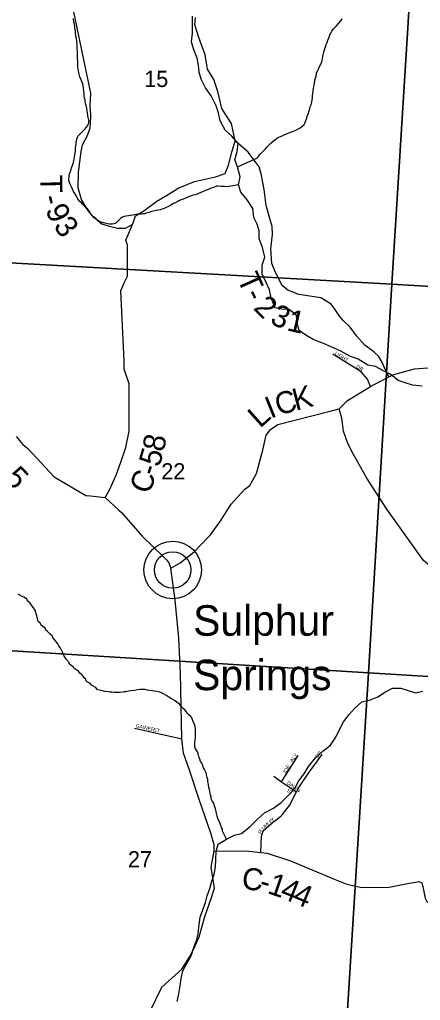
# Model space of a CAD drawing. Extents: x 1949938.81 to 1949945.61, y 152207.65 to 152214.09.
# Drawn here: x 1949942.704 to 1949943.741, y 152210.239 to 152212.776 of the extents above; entities that cross this region are included whole.
import ezdxf

# ---------------------------------------------------------------- set-up
doc = ezdxf.new("R2010")
doc.units = 0
for name, color, linetype in [('GM_X_County_Road', 7, 'Continuous'), ('GM_X_County_Road_Text', 7, 'Continuous'), ('GM_X_Minor_River', 7, 'Continuous'), ('GM_X_Section', 7, 'Continuous'), ('GM_X_Section_Text', 7, 'Continuous'), ('GM_X_Township_Road', 7, 'Continuous'), ('GM_X_Township_Road_Text', 7, 'Continuous'), ('GM_X_Township_ROW', 7, 'Continuous'), ('GM_X_Township_Subdivision', 7, 'Continuous'), ('GM_X_Township_Subdivision_Text', 7, 'Continuous'), ('GM_X_Unincorporated', 7, 'Continuous'), ('GM_X_Unincorporated_Location', 7, 'Continuous'), ('GM_X_Unincorporated_Text', 7, 'Continuous')]:
    doc.layers.add(name, color=color, linetype=linetype)

msp = doc.modelspace()

# ---------------------------------------------------------------- linework, layer by layer
at = {"layer": 'GM_X_County_Road'}
for points in [[(1949942.925, 152211.5397), (1949942.9364, 152211.5595), (1949942.9533, 152211.5975), (1949942.966, 152211.6313), (1949942.9786, 152211.6693), (1949942.9871, 152211.7115), (1949942.987, 152211.8339), (1949942.9744, 152211.8719), (1949942.9744, 152211.893), (1949942.966, 152212.0745), (1949942.9744, 152212.0956), (1949942.9828, 152212.1125), (1949942.9828, 152212.1926), (1949942.9786, 152212.2053), (1949942.9956, 152212.246), (1949942.9997, 152212.2559), (1949943.0039, 152212.2686), (1949943.025, 152212.2813), (1949943.0588, 152212.3066), (1949943.0883, 152212.3235), (1949943.1137, 152212.3404), (1949943.1559, 152212.3572), (1949943.2107, 152212.3699), (1949943.236, 152212.3783), (1949943.2445, 152212.3994), (1949943.2529, 152212.4332), (1949943.2613, 152212.4627), (1949943.252, 152212.5074), (1949943.2376, 152212.5301), (1949943.2273, 152212.5466), (1949943.217, 152212.5899), (1949943.2067, 152212.6209), (1949943.1901, 152212.6477), (1949943.1881, 152212.658), (1949943.184, 152212.6848), (1949943.1675, 152212.7302), (1949943.1572, 152212.7632), (1949943.1592, 152212.7817)], [(1949942.8875, 152211.544), (1949942.925, 152211.5397), (1949942.9607, 152211.5073), (1949942.9671, 152211.5014), (1949943.0208, 152211.4401), (1949943.0754, 152211.3871), (1949943.0839, 152211.3788), (1949943.0897, 152211.3712), (1949943.0949, 152211.357), (1949943.1196, 152211.3709), (1949943.155, 152211.3993), (1949943.1975, 152211.4436), (1949943.2223, 152211.4781), (1949943.2515, 152211.5224), (1949943.2861, 152211.5614), (1949943.2993, 152211.5712), (1949943.317, 152211.6022), (1949943.333, 152211.6624), (1949943.3418, 152211.7014), (1949943.3533, 152211.7156), (1949943.3719, 152211.7288), (1949943.5074, 152211.7634), (1949943.5305, 152211.769), (1949943.5517, 152211.7909), (1949943.6113, 152211.8266), (1949943.6225, 152211.8334), (1949943.6588, 152211.8516), (1949943.6721, 152211.8582), (1949943.7253, 152211.8724), (1949943.7713, 152211.8759)], [(1949944.0481, 152211.1938), (1949944.0481, 152211.1943), (1949944.0437, 152211.2246), (1949944.0338, 152211.2489), (1949944.0225, 152211.2546), (1949943.9414, 152211.2402), (1949943.9251, 152211.2417), (1949943.9054, 152211.2535), (1949943.863, 152211.3067), (1949943.8501, 152211.3154), (1949943.8244, 152211.328), (1949943.7793, 152211.3512), (1949943.749, 152211.3766), (1949943.6543, 152211.5096), (1949943.6025, 152211.5897), (1949943.5635, 152211.6585), (1949943.5517, 152211.6824), (1949943.5415, 152211.7117), (1949943.5373, 152211.7447), (1949943.5305, 152211.769)], [(1949942.6949, 152211.6975), (1949942.7119, 152211.6771), (1949942.7248, 152211.6668), (1949942.7929, 152211.5933), (1949942.8752, 152211.5454), (1949942.8875, 152211.544)], [(1949943.0419, 152210.2106), (1949943.0716, 152210.2729), (1949943.1235, 152210.3193), (1949943.1456, 152210.3552), (1949943.1583, 152210.3801), (1949943.1683, 152210.4033), (1949943.1827, 152210.4558), (1949943.2003, 152210.5045), (1949943.2079, 152210.5293), (1949943.199, 152210.5832), (1949943.207, 152210.6254), (1949943.2073, 152210.6413), (1949943.1998, 152210.6691), (1949943.1672, 152210.7607), (1949943.1429, 152210.8345), (1949943.1282, 152210.8782), (1949943.1236, 152210.9154), (1949943.1198, 152211.0849), (1949943.1161, 152211.1758), (1949943.1066, 152211.2738), (1949943.0949, 152211.357)], [(1949943.207, 152210.6254), (1949943.2969, 152210.625), (1949943.3279, 152210.6214), (1949943.344, 152210.6195), (1949943.405, 152210.6001), (1949943.5201, 152210.5515), (1949943.5506, 152210.539), (1949943.5894, 152210.5306), (1949943.6601, 152210.532), (1949943.7114, 152210.5418), (1949943.728, 152210.5445), (1949943.7364, 152210.5459), (1949943.7447, 152210.5431), (1949943.7474, 152210.5334), (1949943.753, 152210.5029), (1949943.7572, 152210.4945), (1949943.7641, 152210.4904), (1949943.7778, 152210.4892)]]:
    msp.add_lwpolyline(points, dxfattribs=at)
at = {"layer": 'GM_X_Minor_River'}
for points in [[(1949942.8481, 152212.4393), (1949942.8486, 152212.4446), (1949942.8499, 152212.4537), (1949942.85, 152212.4582), (1949942.8508, 152212.4624), (1949942.8517, 152212.467), (1949942.8533, 152212.4719), (1949942.8556, 152212.4752), (1949942.8606, 152212.4809), (1949942.8648, 152212.485), (1949942.8695, 152212.4891), (1949942.873, 152212.4936), (1949942.876, 152212.4969), (1949942.8792, 152212.5014), (1949942.8811, 152212.5052), (1949942.8827, 152212.5101), (1949942.8828, 152212.5158), (1949942.8821, 152212.5196), (1949942.8807, 152212.5261), (1949942.8804, 152212.5295), (1949942.8797, 152212.5345), (1949942.8787, 152212.5402), (1949942.8773, 152212.547), (1949942.877, 152212.5508), (1949942.8752, 152212.5566), (1949942.8738, 152212.5646), (1949942.8735, 152212.5684), (1949942.8721, 152212.573), (1949942.871, 152212.5779), (1949942.8708, 152212.5836), (1949942.8701, 152212.5916), (1949942.8685, 152212.6057), (1949942.8674, 152212.6099), (1949942.8649, 152212.616), (1949942.862, 152212.6225), (1949942.8598, 152212.6286), (1949942.8577, 152212.6355), (1949942.8559, 152212.6439), (1949942.8546, 152212.6541), (1949942.8546, 152212.6583), (1949942.854, 152212.6671), (1949942.8539, 152212.6785), (1949942.8536, 152212.6823), (1949942.8537, 152212.688), (1949942.8534, 152212.6937), (1949942.8527, 152212.7009), (1949942.8525, 152212.7085), (1949942.8526, 152212.7123), (1949942.8519, 152212.7191), (1949942.8506, 152212.7279), (1949942.8495, 152212.7336), (1949942.8485, 152212.7408), (1949942.8482, 152212.7465), (1949942.8465, 152212.7549), (1949942.8466, 152212.7583), (1949942.8455, 152212.7644), (1949942.8445, 152212.7694), (1949942.8431, 152212.7789)], [(1949943.7449, 152211.8281), (1949943.7207, 152211.8304), (1949943.701, 152211.8366), (1949943.6836, 152211.8427), (1949943.664, 152211.858), (1949943.6436, 152211.8687), (1949943.6247, 152211.8786), (1949943.605, 152211.8825), (1949943.5793, 152211.8977), (1949943.5582, 152211.9054), (1949943.5347, 152211.9184), (1949943.5098, 152211.9299), (1949943.4901, 152211.9383), (1949943.4637, 152211.949), (1949943.444, 152211.9597), (1949943.4267, 152211.9719), (1949943.4222, 152211.9909), (1949943.42, 152212.0107), (1949943.4011, 152212.026), (1949943.3822, 152212.0275), (1949943.3648, 152212.0306), (1949943.3543, 152212.0565), (1949943.3499, 152212.077), (1949943.3424, 152212.0945), (1949943.3311, 152212.1173), (1949943.3312, 152212.1409), (1949943.3381, 152212.1613), (1949943.3321, 152212.1864), (1949943.3239, 152212.21), (1949943.324, 152212.2297), (1949943.318, 152212.2472), (1949943.3097, 152212.2647), (1949943.3068, 152212.2875), (1949943.2925, 152212.3103), (1949943.2759, 152212.3301), (1949943.27, 152212.3484), (1949943.2746, 152212.3696), (1949943.2671, 152212.3954), (1949943.2604, 152212.4137), (1949943.2665, 152212.4349), (1949943.2696, 152212.4554), (1949943.2531, 152212.4745), (1949943.2357, 152212.4905), (1949943.2229, 152212.5148), (1949943.2185, 152212.5353), (1949943.2125, 152212.5536), (1949943.1997, 152212.5787), (1949943.1847, 152212.6), (1949943.1734, 152212.622), (1949943.1682, 152212.6403), (1949943.1667, 152212.6585), (1949943.163, 152212.6767), (1949943.154, 152212.7011), (1949943.1481, 152212.7185), (1949943.1512, 152212.7413), (1949943.1514, 152212.7853)], [(1949943.2671, 152212.3954), (1949943.319, 152212.4188), (1949943.3217, 152212.4222), (1949943.3248, 152212.4263), (1949943.3286, 152212.4308), (1949943.3321, 152212.4346), (1949943.3398, 152212.442), (1949943.3441, 152212.4469), (1949943.3487, 152212.4518), (1949943.3541, 152212.457), (1949943.3603, 152212.4626), (1949943.3668, 152212.467), (1949943.3714, 152212.47), (1949943.3763, 152212.4729), (1949943.3832, 152212.4759), (1949943.3886, 152212.4784), (1949943.4, 152212.4836), (1949943.4069, 152212.4861), (1949943.4126, 152212.4879), (1949943.4168, 152212.4897), (1949943.4218, 152212.4919), (1949943.4298, 152212.496), (1949943.4332, 152212.4989), (1949943.4398, 152212.5049), (1949943.4422, 152212.5102), (1949943.4441, 152212.5155), (1949943.4465, 152212.5215), (1949943.4481, 152212.5268), (1949943.4505, 152212.5328), (1949943.4533, 152212.54), (1949943.4545, 152212.5457), (1949943.455, 152212.5491), (1949943.4577, 152212.5555), (1949943.4589, 152212.5589), (1949943.4606, 152212.568), (1949943.4615, 152212.5737), (1949943.4619, 152212.5794), (1949943.4624, 152212.5847), (1949943.4633, 152212.5911), (1949943.4645, 152212.5987), (1949943.4646, 152212.6021), (1949943.4658, 152212.6074), (1949943.4679, 152212.6172), (1949943.468, 152212.6206), (1949943.4696, 152212.6252), (1949943.4716, 152212.6346), (1949943.4721, 152212.638), (1949943.4752, 152212.6456), (1949943.478, 152212.6509), (1949943.4807, 152212.6565), (1949943.4842, 152212.6629), (1949943.4854, 152212.6671), (1949943.4863, 152212.6712), (1949943.4871, 152212.675), (1949943.488, 152212.6807), (1949943.4888, 152212.6852), (1949943.4908, 152212.692), (1949943.4928, 152212.6985), (1949943.4948, 152212.706), (1949943.4972, 152212.712), (1949943.4996, 152212.7173), (1949943.5016, 152212.7234), (1949943.5047, 152212.7309), (1949943.5067, 152212.7366), (1949943.5091, 152212.7411), (1949943.5118, 152212.7467), (1949943.5157, 152212.7524), (1949943.5227, 152212.7595), (1949943.5285, 152212.7658), (1949943.5347, 152212.7729), (1949943.5385, 152212.7786)], [(1949943.27, 152212.3484), (1949943.2404, 152212.3438), (1949943.2339, 152212.3443), (1949943.2245, 152212.3449), (1949943.2165, 152212.3454), (1949943.2124, 152212.3451), (1949943.2066, 152212.3421), (1949943.1998, 152212.34), (1949943.1963, 152212.3385), (1949943.1887, 152212.3356), (1949943.1826, 152212.333), (1949943.1788, 152212.3316), (1949943.1723, 152212.329), (1949943.167, 152212.3268), (1949943.1628, 152212.325), (1949943.1574, 152212.3232), (1949943.1506, 152212.321), (1949943.141, 152212.3174), (1949943.1311, 152212.3138), (1949943.1178, 152212.3079), (1949943.1132, 152212.3061), (1949943.1079, 152212.3035), (1949943.1017, 152212.3002), (1949943.0948, 152212.2965), (1949943.0872, 152212.2921), (1949943.0826, 152212.2899), (1949943.078, 152212.2873), (1949943.0719, 152212.2855), (1949943.0677, 152212.2844), (1949943.0571, 152212.282), (1949943.0499, 152212.2806), (1949943.0461, 152212.2795), (1949943.0426, 152212.2788), (1949943.0377, 152212.277), (1949943.0312, 152212.2752), (1949943.0267, 152212.2741), (1949943.0229, 152212.2734), (1949943.0179, 152212.2731), (1949943.0134, 152212.2728), (1949943.0088, 152212.2725), (1949943.0043, 152212.2718), (1949942.9978, 152212.2704), (1949942.9887, 152212.2691), (1949942.9853, 152212.2687), (1949942.9784, 152212.2677), (1949942.9746, 152212.267), (1949942.9704, 152212.2652), (1949942.9655, 152212.2622), (1949942.9605, 152212.2578), (1949942.9566, 152212.2533), (1949942.9524, 152212.2499), (1949942.9478, 152212.2477), (1949942.9436, 152212.2474), (1949942.936, 152212.2472), (1949942.9315, 152212.2476), (1949942.9274, 152212.2488), (1949942.9206, 152212.2501), (1949942.9149, 152212.2521), (1949942.9112, 152212.254), (1949942.9052, 152212.2575), (1949942.9007, 152212.2614), (1949942.8951, 152212.2661), (1949942.891, 152212.2699), (1949942.8873, 152212.2742), (1949942.8851, 152212.2784), (1949942.8825, 152212.2826), (1949942.8792, 152212.2865), (1949942.8754, 152212.2903), (1949942.8728, 152212.2938), (1949942.8695, 152212.2961), (1949942.8661, 152212.2992), (1949942.8628, 152212.3027), (1949942.8594, 152212.3058), (1949942.8542, 152212.3116), (1949942.8528, 152212.3158), (1949942.8506, 152212.3192), (1949942.8465, 152212.3261), (1949942.8436, 152212.3319), (1949942.8407, 152212.3372), (1949942.8377, 152212.3434), (1949942.8356, 152212.3487), (1949942.833, 152212.3552), (1949942.8312, 152212.3606), (1949942.8322, 152212.3708), (1949942.8322, 152212.3754), (1949942.8342, 152212.381), (1949942.8374, 152212.3897), (1949942.8382, 152212.3931), (1949942.8418, 152212.401), (1949942.8434, 152212.4071), (1949942.8442, 152212.4112), (1949942.8451, 152212.4162), (1949942.8455, 152212.4211), (1949942.8464, 152212.4268), (1949942.8481, 152212.4359), (1949942.8481, 152212.4393)], [(1949943.3145, 152212.4133), (1949943.3141, 152212.4131)], [(1949942.8752, 152211.066), (1949942.8748, 152211.0698), (1949942.8707, 152211.0729), (1949942.8682, 152211.0775), (1949942.8652, 152211.0814), (1949942.86, 152211.0857), (1949942.8559, 152211.0903), (1949942.8446, 152211.0973), (1949942.8436, 152211.1008), (1949942.8402, 152211.1027), (1949942.8324, 152211.1097), (1949942.8317, 152211.1131), (1949942.8239, 152211.1212), (1949942.8213, 152211.1258), (1949942.8183, 152211.1312), (1949942.8147, 152211.14), (1949942.8096, 152211.1496), (1949942.8055, 152211.1561), (1949942.8026, 152211.1608), (1949942.7967, 152211.1692), (1949942.7896, 152211.1777), (1949942.7889, 152211.1811), (1949942.7826, 152211.1858), (1949942.7751, 152211.1939), (1949942.7718, 152211.1966), (1949942.7696, 152211.2016), (1949942.764, 152211.2059), (1949942.7602, 152211.2086), (1949942.7569, 152211.2144), (1949942.7517, 152211.219), (1949942.7499, 152211.2263), (1949942.7482, 152211.2339), (1949942.746, 152211.2412), (1949942.7446, 152211.2454), (1949942.7432, 152211.2499), (1949942.7387, 152211.2553), (1949942.735, 152211.2603), (1949942.7302, 152211.2673), (1949942.7246, 152211.2727), (1949942.7228, 152211.2769), (1949942.7187, 152211.2796), (1949942.7145, 152211.2816), (1949942.7052, 152211.2863), (1949942.6999, 152211.2898)], [(1949943.2388, 152210.6556), (1949943.229, 152210.6764), (1949943.2283, 152210.6821), (1949943.2257, 152210.6859), (1949943.225, 152210.6898), (1949943.2236, 152210.6936), (1949943.2207, 152210.7005), (1949943.2177, 152210.7066), (1949943.2152, 152210.715), (1949943.2135, 152210.7219), (1949943.212, 152210.7276), (1949943.2106, 152210.7345), (1949943.2074, 152210.7444), (1949943.2067, 152210.749), (1949943.2023, 152210.7552), (1949943.1997, 152210.7605), (1949943.1994, 152210.7644), (1949943.1976, 152210.7708), (1949943.1959, 152210.7789), (1949943.1948, 152210.7842), (1949943.1934, 152210.7899), (1949943.1924, 152210.796), (1949943.1917, 152210.8014), (1949943.191, 152210.8048), (1949943.1904, 152210.8105), (1949943.1893, 152210.8151), (1949943.1872, 152210.8224), (1949943.1869, 152210.8258), (1949943.1836, 152210.8323), (1949943.1821, 152210.8358), (1949943.1799, 152210.8404), (1949943.1766, 152210.848), (1949943.1759, 152210.8515), (1949943.1722, 152210.8565), (1949943.1697, 152210.8626), (1949943.1686, 152210.8668), (1949943.1676, 152210.8702), (1949943.1661, 152210.8737), (1949943.1654, 152210.8775), (1949943.1629, 152210.8836), (1949943.1588, 152210.8898), (1949943.1574, 152210.894), (1949943.1568, 152210.9024), (1949943.1568, 152210.9062), (1949943.1577, 152210.9119), (1949943.1589, 152210.9187), (1949943.1592, 152210.9324), (1949943.1589, 152210.9358), (1949943.159, 152210.9419), (1949943.1583, 152210.9464), (1949943.1572, 152210.951), (1949943.1525, 152210.9602), (1949943.151, 152210.9644), (1949943.1492, 152210.9694), (1949943.147, 152210.9729), (1949943.1418, 152210.9771), (1949943.1373, 152210.9818), (1949943.1351, 152210.9864), (1949943.131, 152210.9906), (1949943.1273, 152210.9937), (1949943.1232, 152210.9976), (1949943.1173, 152211.0049), (1949943.1113, 152211.0096), (1949943.1064, 152211.0135), (1949943.0971, 152211.019), (1949943.0896, 152211.0236), (1949943.0817, 152211.0287), (1949943.0761, 152211.0319), (1949943.0727, 152211.0338), (1949943.0663, 152211.0362), (1949943.0587, 152211.0379), (1949943.0519, 152211.0383), (1949943.0474, 152211.0396), (1949943.0399, 152211.0408), (1949943.0338, 152211.0417), (1949943.0285, 152211.0429), (1949943.0248, 152211.0434), (1949943.0202, 152211.0434), (1949943.0145, 152211.0428), (1949943.01, 152211.0425), (1949943.0005, 152211.0407), (1949942.9914, 152211.0394), (1949942.9857, 152211.0383), (1949942.9788, 152211.0373), (1949942.9739, 152211.0366), (1949942.9697, 152211.0363), (1949942.9625, 152211.0357), (1949942.9583, 152211.0354), (1949942.953, 152211.0351), (1949942.9473, 152211.0352), (1949942.9428, 152211.036), (1949942.9371, 152211.0365), (1949942.9334, 152211.0369), (1949942.9247, 152211.0382), (1949942.9145, 152211.0403), (1949942.9054, 152211.0419), (1949942.9014, 152211.0485), (1949942.8897, 152211.054), (1949942.8875, 152211.0578), (1949942.8789, 152211.0625), (1949942.8752, 152211.066)], [(1949943.2012, 152210.547), (1949943.2074, 152210.5653), (1949943.2105, 152210.5835), (1949943.2113, 152210.6033), (1949943.2121, 152210.6238), (1949943.2175, 152210.6428), (1949943.2388, 152210.6556), (1949943.26, 152210.6662), (1949943.2782, 152210.6707), (1949943.301, 152210.6896), (1949943.3185, 152210.7063), (1949943.3375, 152210.7237), (1949943.3603, 152210.7358), (1949943.3808, 152210.751), (1949943.4013, 152210.7714), (1949943.4165, 152210.7889), (1949943.4264, 152210.8063), (1949943.4401, 152210.8245), (1949943.4516, 152210.8435), (1949943.4691, 152210.8662), (1949943.4881, 152210.8837), (1949943.5078, 152210.8988), (1949943.5216, 152210.9193), (1949943.5307, 152210.9375), (1949943.5414, 152210.9595), (1949943.5566, 152210.9785), (1949943.5719, 152210.9959), (1949943.5893, 152211.011), (1949943.609, 152211.0155), (1949943.631, 152211.0238), (1949943.65, 152211.0367), (1949943.6682, 152211.0465), (1949943.6902, 152211.0464), (1949943.7091, 152211.0403), (1949943.7288, 152211.0341), (1949943.747, 152211.0386)], [(1949943.1114, 152210.2356), (1949943.116, 152210.2553), (1949943.1191, 152210.2766), (1949943.1215, 152210.2956), (1949943.1261, 152210.3154), (1949943.136, 152210.3343), (1949943.1474, 152210.3541), (1949943.1543, 152210.3753), (1949943.1612, 152210.3936), (1949943.1658, 152210.411), (1949943.1674, 152210.4285), (1949943.1706, 152210.4536), (1949943.1843, 152210.4916), (1949943.189, 152210.5091), (1949943.1958, 152210.528), (1949943.2012, 152210.547)]]:
    msp.add_lwpolyline(points, dxfattribs=at)
at = {"layer": 'GM_X_Section'}
for points in [[(1949943.7308, 152213.1166), (1949943.6665, 152212.0918), (1949942.5545, 152212.1539), (1949942.623, 152213.1832)], [(1949944.8197, 152213.0519), (1949944.7648, 152212.0263), (1949943.6665, 152212.0918), (1949943.7308, 152213.1166)], [(1949942.5545, 152212.1539), (1949943.6665, 152212.0918), (1949943.6063, 152211.0859), (1949942.4891, 152211.1555)], [(1949943.6665, 152212.0918), (1949944.7648, 152212.0263), (1949944.7104, 152211.0185), (1949943.6063, 152211.0859)], [(1949943.6063, 152211.0859), (1949943.5439, 152210.0754), (1949942.4221, 152210.1447), (1949942.4891, 152211.1555)], [(1949944.7104, 152211.0185), (1949944.6567, 152210.0065), (1949943.5439, 152210.0754), (1949943.6063, 152211.0859)]]:
    msp.add_lwpolyline(points, close=True, dxfattribs=at)
at = {"layer": 'GM_X_Township_Road'}
for points in [[(1949942.9956, 152212.246), (1949942.9768, 152212.2361), (1949942.9567, 152212.2358), (1949942.9367, 152212.2407), (1949942.9166, 152212.2472), (1949942.8954, 152212.2642), (1949942.8802, 152212.2836), (1949942.8636, 152212.3106), (1949942.8553, 152212.3413), (1949942.856, 152212.3812), (1949942.8632, 152212.4347), (1949942.8666, 152212.4525), (1949942.8791, 152212.4761), (1949942.8863, 152212.4962), (1949942.8882, 152212.525), (1949942.8879, 152212.5297)], [(1949943.6588, 152211.8516), (1949943.6396, 152211.8946), (1949943.6332, 152211.9045), (1949943.6199, 152211.9167), (1949943.5968, 152211.9341), (1949943.5756, 152211.9585), (1949943.5586, 152211.9809), (1949943.5408, 152211.9976), (1949943.5294, 152212.012), (1949943.5196, 152212.0272), (1949943.5101, 152212.0401), (1949943.4828, 152212.0564), (1949943.426, 152212.0648), (1949943.3976, 152212.0762), (1949943.3828, 152212.088), (1949943.3662, 152212.1218), (1949943.3563, 152212.1453), (1949943.3537, 152212.1833), (1949943.3583, 152212.2201), (1949943.3571, 152212.2406), (1949943.3526, 152212.2558), (1949943.342, 152212.2956), (1949943.3367, 152212.3363), (1949943.3287, 152212.3773), (1949943.3234, 152212.3955), (1949943.3162, 152212.4061), (1949943.2947, 152212.4334), (1949943.2613, 152212.4627)]]:
    msp.add_lwpolyline(points, dxfattribs=at)
at = {"layer": 'GM_X_Township_ROW'}
msp.add_lwpolyline([(1949942.8879, 152212.5297), (1949942.886, 152212.5528), (1949942.8883, 152212.5858), (1949942.789, 152213.0614), (1949942.8221, 152213.0808), (1949942.8283, 152213.0853)], dxfattribs=at)
at = {"layer": 'GM_X_Township_Subdivision'}
for points in [[(1949943.6113, 152211.8266), (1949943.6035, 152211.846), (1949943.5874, 152211.8646), (1949943.514, 152211.9104)], [(1949943.001, 152210.9431), (1949943.1236, 152210.9154)], [(1949943.3792, 152210.7155), (1949943.3794, 152210.7157), (1949943.3831, 152210.7188), (1949943.4017, 152210.7428), (1949943.4201, 152210.7781), (1949943.4259, 152210.7892), (1949943.4532, 152210.8291), (1949943.4865, 152210.8751)], [(1949943.3816, 152210.8045), (1949943.4249, 152210.8726)], [(1949943.3611, 152210.8184), (1949943.3816, 152210.8045), (1949943.4201, 152210.7781)], [(1949943.3279, 152210.6214), (1949943.3297, 152210.6633), (1949943.3338, 152210.6766), (1949943.3634, 152210.7021), (1949943.3792, 152210.7155)]]:
    msp.add_lwpolyline(points, dxfattribs=at)
at = {"layer": 'GM_X_Unincorporated'}
for radius in [0.0744, 0.0472]:
    msp.add_circle((1949943.0998, 152211.3524), radius, dxfattribs=at)
at = {"layer": 'GM_X_Unincorporated_Location'}
msp.add_line((1949943.0998, 152211.3524), (1949943.0998, 152211.3524), dxfattribs=at)

# ---------------------------------------------------------------- texts
at = {"layer": 'GM_X_County_Road_Text'}
for s, rotation, p in [('K', 14.6874, (1949943.4179, 152211.764)), ('I', 22.1094, (1949943.3532, 152211.7432)), ('C', 15.6334, (1949943.3732, 152211.7515)), ('L', 41.8499, (1949943.3259, 152211.7176)), ('8', 78.9513, (1949943.0766, 152211.656)), ('5', 73.416, (1949943.0652, 152211.6167)), ('5', 314.1169, (1949942.662, 152211.587)), ('C', 67.9757, (1949943.0382, 152211.5457)), ('-', 71.3134, (1949943.057, 152211.5924)), ('C', 353.7827, (1949943.2768, 152210.527)), ('1', 341.2684, (1949943.3425, 152210.5166)), ('-', 344.9773, (1949943.3209, 152210.5224)), ('4', 338.2098, (1949943.3749, 152210.5056)), ('4', 337.4714, (1949943.4072, 152210.4927))]:
    msp.add_text(s, height=0.0568, rotation=rotation, dxfattribs=at).set_placement(p)
at = {"layer": 'GM_X_Section_Text'}
for s, p in [('15', (1949943.0261, 152212.6019)), ('22', (1949943.0703, 152211.5867)), ('27', (1949942.984, 152210.583))]:
    msp.add_text(s, height=0.04186, rotation=0, dxfattribs=at).set_placement(p)
at = {"layer": 'GM_X_Township_Road_Text'}
for s, rotation, p in [('T', 270.63, (1949942.7575, 152212.3742)), ('-', 284.5573, (1949942.76, 152212.3168)), ('9', 294.3067, (1949942.7694, 152212.2843)), ('3', 305.529, (1949942.7898, 152212.2419)), ('T', 294.2171, (1949943.2656, 152212.1064)), ('-', 296.1005, (1949943.2839, 152212.0658)), ('2', 315.2655, (1949943.3062, 152212.0281)), ('3', 335.6918, (1949943.3491, 152211.991)), ('1', 347.2279, (1949943.3928, 152211.9726))]:
    msp.add_text(s, height=0.0568, rotation=rotation, dxfattribs=at).set_placement(p)
at = {"layer": 'GM_X_Township_Subdivision_Text'}
for s, rotation, p in [('LIGHT', 328.5701, (1949943.5179, 152211.9103)), ('DR', 327.9922, (1949943.5737, 152211.8761)), ('GAINER', 346.7591, (1949943.0032, 152210.9455)), ('ST', 348.6904, (1949943.049, 152210.9347)), ('ALY', 57.9953, (1949943.4104, 152210.8539)), ('DR', 53.7428, (1949943.4755, 152210.864)), ('JOE', 58.2394, (1949943.3913, 152210.8231)), ('DAWN', 324.4621, (1949943.3938, 152210.7994)), ('ST', 327.2652, (1949943.3941, 152210.7791)), ('Y', 40.7109, (1949943.3583, 152210.6999)), ('U', 41.5169, (1949943.3344, 152210.6792)), ('M', 40.7181, (1949943.3407, 152210.6847)), ('L', 40.7028, (1949943.3482, 152210.6912)), ('E', 40.7192, (1949943.3533, 152210.6956)), ('P', 72.0596, (1949943.3294, 152210.6684)), ('L', 56.1584, (1949943.3312, 152210.6741))]:
    msp.add_text(s, height=0.00947, rotation=rotation, dxfattribs=at).set_placement(p)
at = {"layer": 'GM_X_Unincorporated_Text'}
for s, p in [('Sulphur', (1949943.1528, 152211.1821)), ('Springs', (1949943.1528, 152211.0413))]:
    msp.add_text(s, height=0.07898, rotation=0, dxfattribs=at).set_placement(p)

doc.saveas('drawing.dxf')
